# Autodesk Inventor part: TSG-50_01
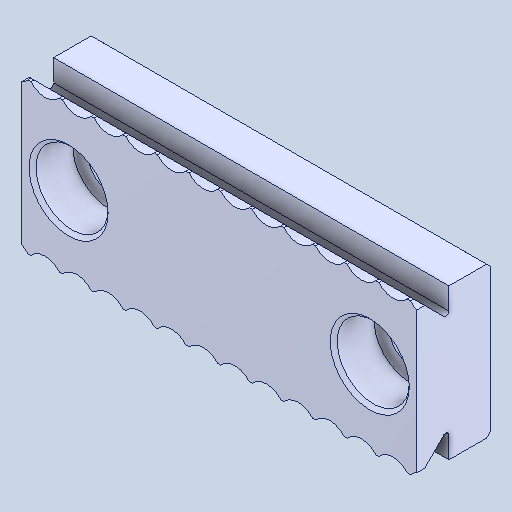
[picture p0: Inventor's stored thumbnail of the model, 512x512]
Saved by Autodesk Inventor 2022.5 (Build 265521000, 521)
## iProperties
Created: 2024-05
Part Number: TSG-50_01
Material: 一般
Document SubType Name: Modeling
Designer: ImaoCorp
Density: 1 g/cm^3
Appearance: 既定
Author: ImaoCorp
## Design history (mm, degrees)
feature "TSG-50_01"
node "ソリッド1"
